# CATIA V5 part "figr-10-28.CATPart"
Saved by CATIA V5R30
Part number: Part1
Bounding box of the stored display mesh (mm): x -60 to 70, y 0 to 100.393, z 0 to 0
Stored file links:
  D:\PROJECTS\CATIA V56R 2020\Resources\Parts File\c10_catia_v5_6r2020_prt\figr-10-28.CATPart
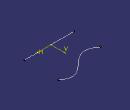
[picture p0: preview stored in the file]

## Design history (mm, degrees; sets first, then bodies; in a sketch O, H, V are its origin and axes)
Body1 (main body)
  Sketch1 on xy-plane, origin (0, 0, 0), H (1, 0, 0), V (0, 1, 0)
    line L1 (-60, 0) -> (70, 0)
    point P1 (-60, 0)
    coincidence: P1 H
    horizontal: L1 H
  Sketch2 on xy-plane, origin (0, 0, 0), H (1, 0, 0), V (0, 1, 0)
    spline S1 through (-60, 70) (-20, 60) (40, 100) (70, 90)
